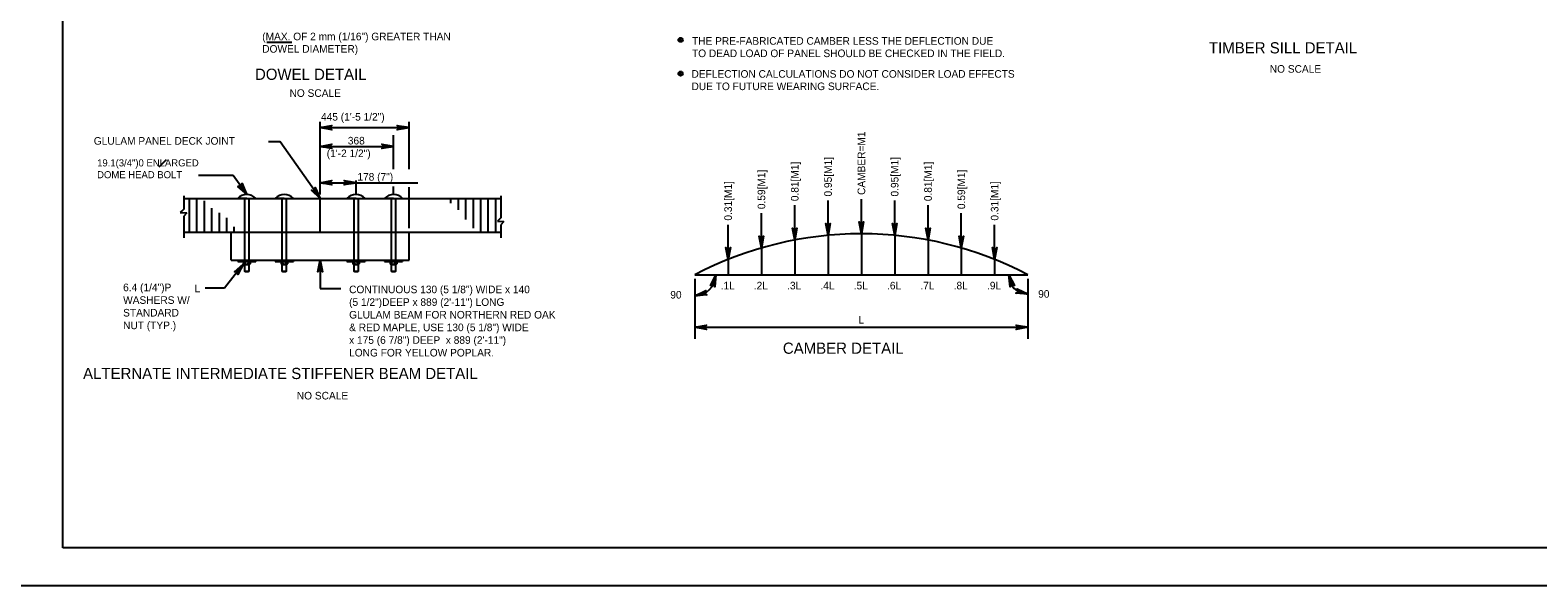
# Model space of a CAD drawing. Extents: x 638268 to 640277, y 295465 to 298435.
# Drawn here: x 639304 to 639899, y 296059 to 296279 of the extents above; entities that cross this region are included whole.
import ezdxf

# ---------------------------------------------------------------- set-up
doc = ezdxf.new("R2010")
doc.units = 0
for name, color, linetype in [('2', 7, 'Continuous'), ('3', 7, 'Continuous'), ('4', 7, 'Continuous'), ('5', 7, 'Continuous'), ('PLT-BNDY', 7, 'Continuous')]:
    doc.layers.add(name, color=color, linetype=linetype)

msp = doc.modelspace()

# ---------------------------------------------------------------- linework, layer by layer
at = {"layer": '2'}
for p, q in [((639316.46, 296074.46), (639316.46, 296638.46)), ((639383.76, 296221.65), (639370.17, 296221.65)), ((639389.18, 296214.12), (639383.76, 296221.65)), ((639364.25, 296208.36), (639362.87, 296207.06)), ((639364.25, 296213.63), (639364.25, 296208.36)), ((639364.25, 296212.53), (639489.61, 296212.53)), ((639389.18, 296212.53), (639385.62, 296212.53)), ((639388.4, 296183.72), (639388.4, 296212.53)), ((639389.18, 296212.53), (639392.75, 296212.53)), ((639389.97, 296212.53), (639389.97, 296183.72)), ((639403.23, 296183.72), (639403.23, 296212.53)), ((639404.81, 296212.53), (639404.81, 296183.72)), ((639418.18, 296199.24), (639418.18, 296212.53)), ((639431.56, 296183.72), (639431.56, 296212.53)), ((639433.14, 296212.53), (639433.14, 296183.72)), ((639446.4, 296183.72), (639446.4, 296212.53)), ((639447.97, 296212.53), (639447.97, 296183.72)), ((639489.61, 296213.63), (639489.61, 296204.92)), ((639362.87, 296207.06), (639365.47, 296206.92)), ((639365.47, 296206.92), (639364.25, 296205.55)), ((639364.25, 296205.55), (639364.25, 296197.04)), ((639489.61, 296204.92), (639488.23, 296203.62)), ((639488.23, 296203.62), (639490.83, 296203.47)), ((639490.83, 296203.47), (639489.61, 296202.11)), ((639489.61, 296202.11), (639489.61, 296197.04)), ((639364.25, 296199.24), (639489.61, 296199.24)), ((639383.05, 296188.22), (639383.05, 296199.24)), ((639453.32, 296188.22), (639453.32, 296199.24)), ((639383.05, 296188.22), (639453.32, 296188.22)), ((639390.49, 296187.63), (639387.88, 296187.63)), ((639387.88, 296187.63), (639387.88, 296186.74)), ((639387.88, 296186.74), (639388.26, 296186.52)), ((639388.26, 296186.52), (639390.11, 296186.52)), ((639388.57, 296186.52), (639388.57, 296187.63)), ((639389.8, 296186.52), (639389.8, 296187.63)), ((639390.11, 296186.52), (639390.49, 296186.74)), ((639390.49, 296187.63), (639390.49, 296186.74)), ((639402.71, 296187.63), (639402.71, 296186.74)), ((639405.32, 296187.63), (639402.71, 296187.63)), ((639402.71, 296186.74), (639403.09, 296186.52)), ((639403.09, 296186.52), (639404.95, 296186.52)), ((639403.41, 296186.52), (639403.41, 296187.63)), ((639404.63, 296186.52), (639404.63, 296187.63)), ((639404.95, 296186.52), (639405.32, 296186.74)), ((639405.32, 296187.63), (639405.32, 296186.74)), ((639431.05, 296187.63), (639431.05, 296186.74)), ((639433.66, 296187.63), (639431.05, 296187.63)), ((639431.05, 296186.74), (639431.42, 296186.52)), ((639431.42, 296186.52), (639433.28, 296186.52)), ((639431.73, 296186.52), (639431.73, 296187.63)), ((639432.97, 296186.52), (639432.97, 296187.63)), ((639433.28, 296186.52), (639433.66, 296186.74)), ((639433.66, 296187.63), (639433.66, 296186.74)), ((639445.88, 296187.63), (639445.88, 296186.74)), ((639448.49, 296187.63), (639445.88, 296187.63)), ((639445.88, 296186.74), (639446.26, 296186.52)), ((639446.26, 296186.52), (639448.11, 296186.52)), ((639446.57, 296186.52), (639446.57, 296187.63)), ((639447.8, 296186.52), (639447.8, 296187.63)), ((639448.11, 296186.52), (639448.49, 296186.74)), ((639448.49, 296187.63), (639448.49, 296186.74)), ((639389.97, 296183.72), (639388.4, 296183.72)), ((639388.59, 296183.52), (639388.4, 296183.72)), ((639389.78, 296183.52), (639388.59, 296183.52)), ((639389.97, 296183.72), (639389.78, 296183.52)), ((639403.43, 296183.52), (639403.23, 296183.72)), ((639404.81, 296183.72), (639403.23, 296183.72)), ((639404.61, 296183.52), (639403.43, 296183.52)), ((639404.81, 296183.72), (639404.61, 296183.52)), ((639431.76, 296183.52), (639431.56, 296183.72)), ((639433.14, 296183.72), (639431.56, 296183.72)), ((639432.94, 296183.52), (639431.76, 296183.52)), ((639433.14, 296183.72), (639432.94, 296183.52)), ((639446.59, 296183.52), (639446.4, 296183.72)), ((639447.97, 296183.72), (639446.4, 296183.72)), ((639447.78, 296183.52), (639446.59, 296183.52)), ((639447.97, 296183.72), (639447.78, 296183.52)), ((639566.25, 296182.41), (639697.91, 296182.41)), ((640102.46, 296074.46), (639316.46, 296074.46))]:
    msp.add_line(p, q, dxfattribs=at)
msp.add_lwpolyline([(639389.18, 296214.12), (639387.47, 296218.43), (639385.64, 296217.12)], close=True, dxfattribs=at)
for centre, radius, start, end in [((639389.19, 296209.33), 4.79, 41.87015, 138.12985), ((639388.53, 296187.6), 1.08, 233, 307), ((639389.84, 296187.6), 1.08, 233, 307), ((639403.37, 296187.6), 1.08, 233, 307), ((639404.67, 296187.6), 1.08, 233, 307), ((639431.7, 296187.6), 1.08, 233, 307), ((639433, 296187.6), 1.08, 233, 307), ((639446.53, 296187.6), 1.08, 233, 307), ((639447.84, 296187.6), 1.08, 233, 307)]:
    msp.add_arc(centre, radius, start, end, dxfattribs=at)
at = {"layer": '3'}
for p, q in [((639397.15, 296274.37), (639407.03, 296274.37)), ((639354.56, 296225.12), (639357.43, 296227.99)), ((639380.34, 296177.17), (639372.71, 296177.17)), ((639418.19, 296177.03), (639426.4, 296177.03))]:
    msp.add_line(p, q, dxfattribs=at)
for points in [[(639418.18, 296212.53), (639402.35, 296235.01), (639397.74, 296235.01)], [(639389.18, 296214.12), (639385.75, 296217.39), (639386.16, 296217.25), (639386.52, 296217.28), (639386.81, 296217.42), (639387.03, 296217.64), (639387.18, 296217.98), (639387.17, 296218.42), (639389.18, 296214.12), (639387.18, 296217.98), (639387.03, 296217.64), (639389.18, 296214.12), (639386.81, 296217.42), (639386.52, 296217.28), (639389.18, 296214.12), (639386.16, 296217.25)], [(639418.18, 296212.53), (639414.78, 296215.84), (639415.2, 296215.69), (639415.56, 296215.72), (639415.84, 296215.85), (639416.07, 296216.07), (639416.22, 296216.41), (639416.22, 296216.84), (639418.18, 296212.53), (639416.22, 296216.41), (639416.07, 296216.07), (639418.18, 296212.53), (639415.84, 296215.85), (639415.56, 296215.72), (639418.18, 296212.53), (639415.2, 296215.69)], [(639387.88, 296186.74), (639380.34, 296177.17)], [(639387.88, 296186.74), (639385.68, 296182.54), (639385.71, 296182.97), (639385.58, 296183.31), (639385.37, 296183.55), (639385.09, 296183.7), (639384.73, 296183.75), (639384.31, 296183.62), (639387.88, 296186.74), (639384.73, 296183.75), (639385.09, 296183.7), (639387.88, 296186.74), (639385.37, 296183.55), (639385.58, 296183.31), (639387.88, 296186.74), (639385.71, 296182.97)], [(639418.18, 296188.22), (639419.06, 296183.56), (639418.81, 296183.92), (639418.5, 296184.1), (639418.18, 296184.16), (639417.87, 296184.1), (639417.56, 296183.92), (639417.31, 296183.56), (639418.18, 296188.22), (639417.56, 296183.92), (639417.87, 296184.1), (639418.18, 296188.22), (639418.18, 296184.16), (639418.5, 296184.1), (639418.18, 296188.22), (639418.81, 296183.92)], [(639418.18, 296188.22), (639418.18, 296177.03)]]:
    msp.add_lwpolyline(points, dxfattribs=at)
for points in [[(639418.18, 296212.53), (639418.12, 296212.63), (639418.08, 296212.59)], [(639387.88, 296186.74), (639387.78, 296186.66), (639387.83, 296186.63)], [(639418.18, 296188.22), (639418.16, 296188.1), (639418.21, 296188.1)]]:
    msp.add_lwpolyline(points, close=True, dxfattribs=at)
at = {"layer": '4'}
for p, q in [((639605.75, 296196.15), (639605.75, 296182.41)), ((639618.91, 296198), (639618.91, 296182.41)), ((639632.08, 296198.61), (639632.08, 296182.41)), ((639645.25, 296198), (639645.25, 296182.41)), ((639658.41, 296196.15), (639658.41, 296182.41)), ((639592.58, 296193), (639592.58, 296182.41)), ((639671.58, 296193), (639671.58, 296182.41)), ((639579.41, 296188.47), (639579.41, 296182.41)), ((639684.75, 296188.47), (639684.75, 296182.41)), ((639579.41, 296182.41), (639579.41, 296182.41)), ((639592.58, 296182.41), (639592.58, 296182.41)), ((639605.75, 296182.41), (639605.75, 296182.41)), ((639618.91, 296182.41), (639618.91, 296182.41)), ((639632.08, 296182.41), (639632.08, 296182.41)), ((639645.25, 296182.41), (639645.25, 296182.41)), ((639658.41, 296182.41), (639658.41, 296182.41)), ((639671.58, 296182.41), (639671.58, 296182.41)), ((639684.75, 296182.41), (639684.75, 296182.41))]:
    msp.add_line(p, q, dxfattribs=at)
msp.add_arc((639632.08, 296056.75), 141.86, 62.35093, 117.64907, dxfattribs=at)
at = {"layer": '5'}
for p, q in [((639418.18, 296214.07), (639418.18, 296242.79)), ((639418.18, 296240.58), (639453.32, 296240.58)), ((639453.32, 296224.14), (639453.32, 296242.79)), ((639453.32, 296233.07), (639453.32, 296242.79)), ((639453.32, 296240.58), (639453.32, 296240.58)), ((639418.18, 296214.07), (639418.18, 296237.59)), ((639418.18, 296233.16), (639447.18, 296233.16)), ((639447.18, 296233.16), (639447.18, 296233.16)), ((639447.19, 296232.03), (639447.19, 296237.59)), ((639447.19, 296224.14), (639447.19, 296234.08)), ((639418.18, 296214.07), (639418.18, 296223.22)), ((639418.19, 296218.79), (639456.79, 296218.79)), ((639432.35, 296214.07), (639432.35, 296219.6)), ((639432.35, 296218.79), (639432.35, 296218.79)), ((639447.19, 296214.07), (639447.19, 296217.24)), ((639453.32, 296200.78), (639453.32, 296217)), ((639366.53, 296199.24), (639366.53, 296212.53)), ((639369.48, 296199.25), (639369.48, 296212.53)), ((639372.44, 296199.25), (639372.44, 296211.68)), ((639375.39, 296199.25), (639375.39, 296208.68)), ((639404.02, 296212.53), (639400.45, 296212.53)), ((639404.02, 296212.53), (639407.59, 296212.53)), ((639418.18, 296212.53), (639418.18, 296212.53)), ((639432.35, 296212.53), (639428.78, 296212.53)), ((639432.35, 296212.53), (639435.92, 296212.53)), ((639432.35, 296212.53), (639432.35, 296212.53)), ((639447.18, 296212.53), (639443.62, 296212.53)), ((639447.18, 296212.53), (639450.75, 296212.53)), ((639447.18, 296212.53), (639447.18, 296212.53)), ((639469.88, 296210.66), (639469.88, 296212.53)), ((639472.83, 296208.12), (639472.83, 296212.53)), ((639475.78, 296204.29), (639475.78, 296212.53)), ((639478.73, 296200.89), (639478.73, 296212.53)), ((639481.69, 296199.3), (639481.69, 296212.53)), ((639484.64, 296199.24), (639484.64, 296212.53)), ((639487.59, 296199.24), (639487.59, 296212.53)), ((639605.75, 296196.15), (639605.75, 296209.86)), ((639618.91, 296198), (639618.91, 296211.71)), ((639632.08, 296198.61), (639632.08, 296212.32)), ((639645.25, 296198), (639645.25, 296211.71)), ((639658.41, 296196.15), (639658.41, 296209.86)), ((639363.58, 296207.02), (639363.58, 296207.72)), ((639378.34, 296199.25), (639378.34, 296206.89)), ((639381.29, 296199.25), (639381.29, 296204.94)), ((639490.55, 296203.15), (639490.55, 296203.49)), ((639579.41, 296188.47), (639579.41, 296202.18)), ((639592.58, 296193), (639592.58, 296206.71)), ((639671.58, 296193), (639671.58, 296206.71)), ((639684.75, 296188.47), (639684.75, 296202.18)), ((639384.25, 296199.26), (639384.25, 296201.3)), ((639387.2, 296199.26), (639387.2, 296199.37)), ((639453.32, 296199.24), (639453.32, 296199.24)), ((639385.62, 296188.22), (639385.62, 296187.63)), ((639385.62, 296187.92), (639392.75, 296187.92)), ((639385.62, 296187.63), (639392.75, 296187.63)), ((639392.75, 296188.22), (639392.75, 296187.63)), ((639400.45, 296188.22), (639400.45, 296187.63)), ((639400.45, 296187.92), (639407.59, 296187.92)), ((639400.45, 296187.63), (639407.59, 296187.63)), ((639407.59, 296188.22), (639407.59, 296187.63)), ((639428.78, 296188.22), (639428.78, 296187.63)), ((639428.78, 296187.92), (639435.92, 296187.92)), ((639428.78, 296187.63), (639435.92, 296187.63)), ((639435.92, 296188.22), (639435.92, 296187.63)), ((639443.62, 296188.22), (639443.62, 296187.63)), ((639443.62, 296187.92), (639450.75, 296187.92)), ((639443.62, 296187.63), (639450.75, 296187.63)), ((639450.75, 296188.22), (639450.75, 296187.63)), ((639566.25, 296180.85), (639566.25, 296157.15)), ((639697.91, 296180.85), (639697.91, 296157.15)), ((639566.25, 296161.65), (639697.91, 296161.65))]:
    msp.add_line(p, q, dxfattribs=at)
for points in [[(639418.18, 296240.58), (639422.85, 296241.45), (639422.49, 296241.2), (639422.3, 296240.89), (639422.25, 296240.58), (639422.3, 296240.27), (639422.49, 296239.95), (639422.85, 296239.71), (639418.18, 296240.58), (639422.49, 296239.95), (639422.3, 296240.27), (639418.18, 296240.58), (639422.25, 296240.58), (639422.3, 296240.89), (639418.18, 296240.58), (639422.49, 296241.2)], [(639453.32, 296240.58), (639448.66, 296239.71), (639449.02, 296239.95), (639449.21, 296240.27), (639449.26, 296240.58), (639449.21, 296240.89), (639449.02, 296241.2), (639448.66, 296241.45), (639453.32, 296240.58), (639449.02, 296241.2), (639449.21, 296240.89), (639453.32, 296240.58), (639449.26, 296240.58), (639449.21, 296240.27), (639453.32, 296240.58), (639449.02, 296239.95)], [(639418.18, 296233.16), (639422.85, 296234.04), (639422.49, 296233.79), (639422.3, 296233.48), (639422.25, 296233.16), (639422.3, 296232.85), (639422.49, 296232.54), (639422.85, 296232.29), (639418.18, 296233.16), (639422.49, 296232.54), (639422.3, 296232.85), (639418.18, 296233.16), (639422.25, 296233.16), (639422.3, 296233.48), (639418.18, 296233.16), (639422.49, 296233.79)], [(639447.18, 296233.16), (639442.52, 296232.29), (639442.88, 296232.54), (639443.07, 296232.85), (639443.12, 296233.16), (639443.07, 296233.48), (639442.88, 296233.79), (639442.52, 296234.04), (639447.18, 296233.16), (639442.88, 296233.79), (639443.07, 296233.48), (639447.18, 296233.16), (639443.12, 296233.16), (639443.07, 296232.85), (639447.18, 296233.16), (639442.88, 296232.54)], [(639418.18, 296218.79), (639422.85, 296219.66), (639422.49, 296219.41), (639422.3, 296219.1), (639422.25, 296218.79), (639422.3, 296218.48), (639422.49, 296218.16), (639422.85, 296217.92), (639418.18, 296218.79), (639422.49, 296218.16), (639422.3, 296218.48), (639418.18, 296218.79), (639422.25, 296218.79), (639422.3, 296219.1), (639418.18, 296218.79), (639422.49, 296219.41)], [(639432.35, 296218.79), (639427.69, 296217.92), (639428.05, 296218.16), (639428.23, 296218.48), (639428.29, 296218.79), (639428.23, 296219.1), (639428.05, 296219.41), (639427.69, 296219.66), (639432.35, 296218.79), (639428.05, 296219.41), (639428.23, 296219.1), (639432.35, 296218.79), (639428.29, 296218.79), (639428.23, 296218.48), (639432.35, 296218.79), (639428.05, 296218.16)], [(639618.91, 296198), (639618.04, 296202.66), (639618.29, 296202.3), (639618.6, 296202.12), (639618.91, 296202.06), (639619.22, 296202.12), (639619.54, 296202.3), (639619.79, 296202.66), (639618.91, 296198), (639619.54, 296202.3), (639619.22, 296202.12), (639618.91, 296198), (639618.91, 296202.06), (639618.6, 296202.12), (639618.91, 296198), (639618.29, 296202.3)], [(639632.08, 296198.61), (639631.21, 296203.27), (639631.45, 296202.91), (639631.77, 296202.73), (639632.08, 296202.67), (639632.39, 296202.73), (639632.7, 296202.91), (639632.95, 296203.27), (639632.08, 296198.61), (639632.7, 296202.91), (639632.39, 296202.73), (639632.08, 296198.61), (639632.08, 296202.67), (639631.77, 296202.73), (639632.08, 296198.61), (639631.45, 296202.91)], [(639645.25, 296198), (639644.37, 296202.66), (639644.62, 296202.3), (639644.93, 296202.12), (639645.25, 296202.06), (639645.56, 296202.12), (639645.87, 296202.3), (639646.12, 296202.66), (639645.25, 296198), (639645.87, 296202.3), (639645.56, 296202.12), (639645.25, 296198), (639645.25, 296202.06), (639644.93, 296202.12), (639645.25, 296198), (639644.62, 296202.3)], [(639592.58, 296193), (639591.71, 296197.66), (639591.95, 296197.31), (639592.27, 296197.12), (639592.58, 296197.07), (639592.89, 296197.12), (639593.2, 296197.31), (639593.45, 296197.66), (639592.58, 296193), (639593.2, 296197.31), (639592.89, 296197.12), (639592.58, 296193), (639592.58, 296197.07), (639592.27, 296197.12), (639592.58, 296193), (639591.95, 296197.31)], [(639605.75, 296196.15), (639604.87, 296200.81), (639605.12, 296200.45), (639605.43, 296200.26), (639605.75, 296200.21), (639606.06, 296200.26), (639606.37, 296200.45), (639606.62, 296200.81), (639605.75, 296196.15), (639606.37, 296200.45), (639606.06, 296200.26), (639605.75, 296196.15), (639605.75, 296200.21), (639605.43, 296200.26), (639605.75, 296196.15), (639605.12, 296200.45)], [(639658.41, 296196.15), (639657.54, 296200.81), (639657.79, 296200.45), (639658.1, 296200.26), (639658.41, 296200.21), (639658.72, 296200.26), (639659.04, 296200.45), (639659.29, 296200.81), (639658.41, 296196.15), (639659.04, 296200.45), (639658.72, 296200.26), (639658.41, 296196.15), (639658.41, 296200.21), (639658.1, 296200.26), (639658.41, 296196.15), (639657.79, 296200.45)], [(639671.58, 296193), (639670.71, 296197.66), (639670.95, 296197.31), (639671.27, 296197.12), (639671.58, 296197.07), (639671.89, 296197.12), (639672.2, 296197.31), (639672.45, 296197.66), (639671.58, 296193), (639672.2, 296197.31), (639671.89, 296197.12), (639671.58, 296193), (639671.58, 296197.07), (639671.27, 296197.12), (639671.58, 296193), (639670.95, 296197.31)], [(639579.41, 296188.47), (639578.54, 296193.13), (639578.79, 296192.78), (639579.1, 296192.59), (639579.41, 296192.54), (639579.72, 296192.59), (639580.04, 296192.78), (639580.29, 296193.13), (639579.41, 296188.47), (639580.04, 296192.78), (639579.72, 296192.59), (639579.41, 296188.47), (639579.41, 296192.54), (639579.1, 296192.59), (639579.41, 296188.47), (639578.79, 296192.78)], [(639684.75, 296188.47), (639683.87, 296193.13), (639684.12, 296192.78), (639684.43, 296192.59), (639684.75, 296192.54), (639685.06, 296192.59), (639685.37, 296192.78), (639685.62, 296193.13), (639684.75, 296188.47), (639685.37, 296192.78), (639685.06, 296192.59), (639684.75, 296188.47), (639684.75, 296192.54), (639684.43, 296192.59), (639684.75, 296188.47), (639684.12, 296192.78)], [(639574.53, 296182.41), (639574.15, 296177.68), (639574.01, 296178.09), (639573.75, 296178.35), (639573.47, 296178.48), (639573.15, 296178.52), (639572.8, 296178.42), (639572.47, 296178.14), (639574.53, 296182.41), (639572.8, 296178.42), (639573.15, 296178.52), (639574.53, 296182.41), (639573.47, 296178.48), (639573.75, 296178.35), (639574.53, 296182.41), (639574.01, 296178.09)], [(639690.3, 296182.41), (639692.53, 296178.23), (639692.18, 296178.49), (639691.83, 296178.58), (639691.51, 296178.54), (639691.23, 296178.39), (639690.99, 296178.12), (639690.86, 296177.7), (639690.3, 296182.41), (639690.99, 296178.12), (639691.23, 296178.39), (639690.3, 296182.41), (639691.51, 296178.54), (639691.83, 296178.58), (639690.3, 296182.41), (639692.18, 296178.49)], [(639566.25, 296174.14), (639570.54, 296176.16), (639570.26, 296175.83), (639570.15, 296175.48), (639570.18, 296175.17), (639570.31, 296174.88), (639570.57, 296174.62), (639570.98, 296174.47), (639566.25, 296174.14), (639570.57, 296174.62), (639570.31, 296174.88), (639566.25, 296174.14), (639570.18, 296175.17), (639570.15, 296175.48), (639566.25, 296174.14), (639570.26, 296175.83)], [(639697.9, 296174.74), (639693.18, 296175.2), (639693.6, 296175.34), (639693.86, 296175.59), (639694, 296175.87), (639694.04, 296176.19), (639693.95, 296176.54), (639693.67, 296176.88), (639697.9, 296174.74), (639693.95, 296176.54), (639694.04, 296176.19), (639697.9, 296174.74), (639694, 296175.87), (639693.86, 296175.59), (639697.9, 296174.74), (639693.6, 296175.34)], [(639566.25, 296161.65), (639570.91, 296162.52), (639570.55, 296162.28), (639570.36, 296161.96), (639570.31, 296161.65), (639570.36, 296161.34), (639570.55, 296161.03), (639570.91, 296160.78), (639566.25, 296161.65), (639570.55, 296161.03), (639570.36, 296161.34), (639566.25, 296161.65), (639570.31, 296161.65), (639570.36, 296161.96), (639566.25, 296161.65), (639570.55, 296162.28)], [(639697.91, 296161.65), (639693.25, 296160.78), (639693.61, 296161.03), (639693.8, 296161.34), (639693.85, 296161.65), (639693.8, 296161.96), (639693.61, 296162.28), (639693.25, 296162.52), (639697.91, 296161.65), (639693.61, 296162.28), (639693.8, 296161.96), (639697.91, 296161.65), (639693.85, 296161.65), (639693.8, 296161.34), (639697.91, 296161.65), (639693.61, 296161.03)]]:
    msp.add_lwpolyline(points, dxfattribs=at)
for points in [[(639421.14, 296241.07), (639421.14, 296240.08), (639418.18, 296240.58)], [(639450.37, 296241.07), (639450.37, 296240.08), (639453.32, 296240.58)], [(639421.14, 296233.66), (639421.14, 296232.67), (639418.18, 296233.16)], [(639444.23, 296233.66), (639444.23, 296232.67), (639447.18, 296233.16)], [(639421.14, 296219.28), (639421.14, 296218.3), (639418.18, 296218.79)], [(639429.4, 296219.28), (639429.4, 296218.3), (639432.35, 296218.79)]]:
    msp.add_lwpolyline(points, close=True, dxfattribs=at)
for centre, radius in [((639560.62, 296275.24), 0.833), ((639560.62, 296275.24), 0.417), ((639560.62, 296261.93), 0.833), ((639560.62, 296261.93), 0.417)]:
    msp.add_circle(centre, radius, dxfattribs=at)
for centre, radius, start, end in [((639404.02, 296209.33), 4.79, 41.87015, 138.12985), ((639432.35, 296209.33), 4.79, 41.87015, 138.12985), ((639447.19, 296209.33), 4.79, 41.87015, 138.12985), ((639566.24, 296182.41), 8.24, 269.99986, 359.99461), ((639697.91, 296182.41), 7.62, 180.00584, 270.00516)]:
    msp.add_arc(centre, radius, start, end, dxfattribs=at)
at = {"layer": 'PLT-BNDY'}
msp.add_lwpolyline([(639276.46, 296653.46), (640117.46, 296653.46), (640117.46, 296059.46), (639276.46, 296059.46)], close=True, dxfattribs=at)

# ---------------------------------------------------------------- texts
at = {"layer": '3'}
for s, height, p in [('(MAX. OF 2 mm (1/16") GREATER THAN', 3, (639395.29, 296275.08)), ('TIMBER SILL DETAIL', 4.4292, (639769.44, 296269.9)), ('DOWEL DIAMETER)', 3, (639395.29, 296270.19)), ('DOWEL DETAIL', 4.4292, (639392.42, 296259.44)), ('NO SCALE', 3, (639793.48, 296262.27)), ('NO SCALE', 3, (639406.08, 296252.72)), ('GLULAM PANEL DECK JOINT', 3, (639328.73, 296233.82)), ('19.1(3/4")0 ENLARGED', 2.8082, (639330.04, 296225.23)), ('DOME HEAD BOLT', 2.8082, (639330.04, 296220.55)), ('6.4 (1/4")P', 3, (639340.32, 296175.91)), ('L', 3, (639368.57, 296175.5)), ('CONTINUOUS 130 (5 1/8") WIDE x 140', 3, (639429.63, 296175.11)), ('WASHERS W/ ', 3, (639340.32, 296170.91)), ('(5 1/2")DEEP x 889 (2\'-11") LONG', 3, (639429.63, 296170.11)), ('STANDARD', 3, (639340.32, 296165.91)), ('GLULAM BEAM FOR NORTHERN RED OAK', 3, (639429.63, 296165.11)), ('NUT (TYP.)', 3, (639340.32, 296160.91)), ('& RED MAPLE, USE 130 (5 1/8") WIDE', 3, (639429.63, 296160.11)), ('x 175 (6 7/8") DEEP  x 889 (2\'-11")', 3, (639429.63, 296155.11)), ('LONG FOR YELLOW POPLAR.', 3, (639429.63, 296150.11)), ('ALTERNATE INTERMEDIATE STIFFENER BEAM DETAIL', 4.4292, (639324.49, 296141.19)), ('NO SCALE', 3, (639408.96, 296133.13))]:
    msp.add_text(s, height=height, dxfattribs=at).set_placement(p)
at = {"layer": '5'}
for s, height, p in [('THE PRE-FABRICATED CAMBER LESS THE DEFLECTION DUE', 3, (639565.14, 296273.33)), ('TO DEAD LOAD OF PANEL SHOULD BE CHECKED IN THE FIELD.', 3, (639565.14, 296268.43)), ('DEFLECTION CALCULATIONS DO NOT CONSIDER LOAD EFFECTS', 3, (639564.93, 296260.29)), ('DUE TO FUTURE WEARING SURFACE.', 3, (639564.93, 296255.39)), ('445 (1\'-5 1/2")', 3, (639418.52, 296243.34)), ('(1\'-2 1/2")', 3, (639420.78, 296228.91)), ('368', 3, (639429.12, 296233.91)), ('178 (7")', 3, (639432.9, 296219.62)), ('.1L', 3, (639576.48, 296176.63)), ('.2L', 3, (639589.56, 296176.63)), ('.3L', 3, (639602.73, 296176.63)), ('.4L', 3, (639615.89, 296176.63)), ('.5L', 3, (639629.06, 296176.63)), ('.6L', 3, (639642.23, 296176.63)), ('.7L', 3, (639655.39, 296176.63)), ('.8L', 3, (639668.56, 296176.63)), ('.9L', 3, (639681.73, 296176.63)), ('90', 3, (639556.56, 296173.01)), ('90', 3, (639701.95, 296173.34)), ('L', 3, (639630.91, 296163.12)), ('CAMBER DETAIL', 4.4292, (639601.05, 296151.17))]:
    msp.add_text(s, height=height, dxfattribs=at).set_placement(p)
for s, p in [('CAMBER=M1', (639633.58, 296213.95)), ('0.81[M1]', (639607.25, 296211.49)), ('0.95[M1]', (639620.41, 296213.34)), ('0.95[M1]', (639646.74, 296213.34)), ('0.81[M1]', (639659.91, 296211.49)), ('0.59[M1]', (639594.08, 296208.34)), ('0.59[M1]', (639673.08, 296208.34)), ('0.31[M1]', (639580.91, 296203.81)), ('0.31[M1]', (639686.24, 296203.81))]:
    msp.add_text(s, height=3, rotation=90, dxfattribs=at).set_placement(p)

doc.saveas('drawing.dxf')
